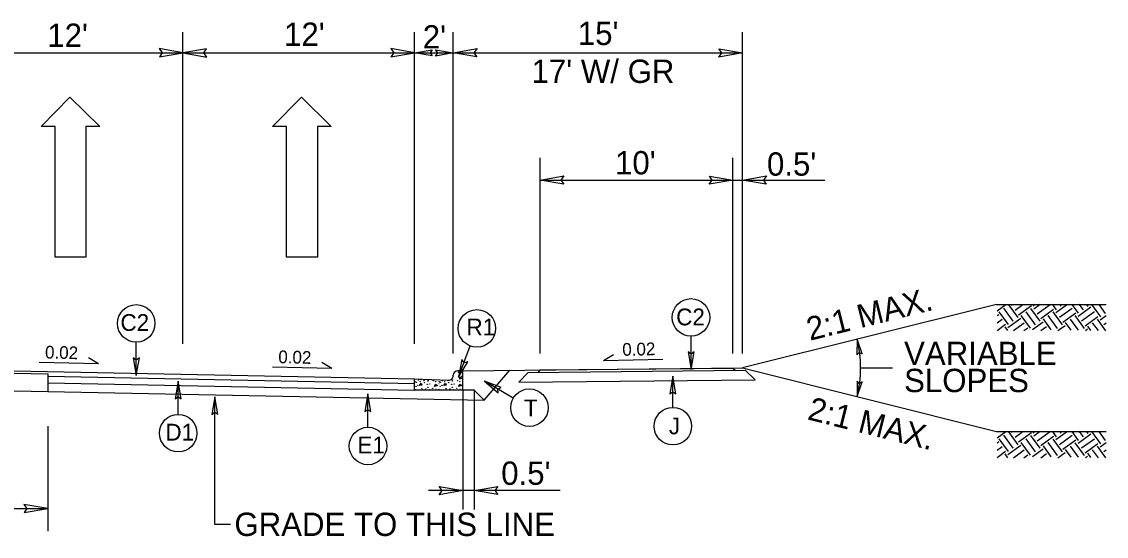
# Model space of a CAD drawing. Extents: x 3025871 to 3026431, y 707165 to 707825.
# Drawn here: x 3026374.6 to 3026430.8, y 707640.9 to 707667.6 of the extents above; entities that cross this region are included whole.
import ezdxf

# ---------------------------------------------------------------- set-up
doc = ezdxf.new("R2010")
doc.units = 0
for name, color, linetype in [('Prop Drainage Structure Junction Box with Manhole CELL', 7, 'Continuous'), ('Prop Drainage Structure Junction Box with Slab Lid TB 840 34 CELL', 7, 'Continuous'), ('Prop Drainage Structure Plot Symbol 50 Scale', 7, 'Continuous'), ('Prop Pavement Schedule Description CELL', 7, 'Continuous'), ('Sheet Data Field CELL', 7, 'Continuous'), ('Sheet Plot Border Inside CELL', 7, 'Continuous'), ('Sheet Sticker Incomplete CELL', 7, 'Continuous'), ('Sheet Typical CELL', 7, 'Continuous'), ('Typical Arrow Superelevation CELL', 7, 'Continuous'), ('Typical Grade Point Symbol CELL', 7, 'Continuous'), ('Typical Text Centerline CELL', 7, 'Continuous'), ('Typical Text Grade Point CELL', 7, 'Continuous')]:
    doc.layers.add(name, color=color, linetype=linetype)

msp = doc.modelspace()

# ---------------------------------------------------------------- linework, layer by layer
at = {"layer": 'Prop Drainage Structure Junction Box with Manhole CELL'}
msp.add_line((3026375.914, 707648.426), (3026398.523, 707647.974), dxfattribs=at)
at = {"layer": 'Prop Drainage Structure Junction Box with Slab Lid TB 840 34 CELL'}
for p, q in [((3026382.912, 707650.898), (3026382.912, 707667.04)), ((3026394.912, 707650.898), (3026394.912, 707667.04)), ((3026396.92, 707650.399), (3026396.92, 707667.04)), ((3026411.92, 707650.399), (3026411.92, 707667.04)), ((3026362.162, 707665.973), (3026394.912, 707665.973)), ((3026394.912, 707665.973), (3026411.92, 707665.973)), ((3026401.42, 707650.399), (3026401.42, 707660.529)), ((3026411.42, 707650.399), (3026411.42, 707660.529)), ((3026401.42, 707659.381), (3026416.178, 707659.381)), ((3026418.036, 707649.648), (3026419.692, 707649.648)), ((3026397.421, 707648.502), (3026397.421, 707642.305)), ((3026398.006, 707648.514), (3026398.006, 707642.305)), ((3026375.9, 707646.63), (3026375.9, 707641.192)), ((3026402.454, 707643.295), (3026395.634, 707643.294)), ((3026348.144, 707642.363), (3026375.9, 707642.363)), ((3026385.375, 707641.531), (3026384.564, 707641.531))]:
    msp.add_line(p, q, dxfattribs=at)
msp.add_arc((3026411.92, 707649.648), 6.116, 345.9638, 14.0362, dxfattribs=at)
at = {"layer": 'Prop Drainage Structure Plot Symbol 50 Scale'}
for p, q in [((3026397.421, 707649.506), (3026397.16, 707649.506)), ((3026397.421, 707648.502), (3026397.421, 707649.506)), ((3026394.912, 707648.502), (3026394.912, 707649.088)), ((3026394.912, 707649.088), (3026396.669, 707649.015)), ((3026395.174, 707648.743), (3026395.261, 707648.863)), ((3026395.295, 707648.749), (3026395.174, 707648.743)), ((3026395.261, 707648.863), (3026395.295, 707648.749)), ((3026395.942, 707648.692), (3026396.005, 707648.807)), ((3026396.108, 707648.731), (3026395.942, 707648.692)), ((3026396.005, 707648.807), (3026396.108, 707648.731)), ((3026396.428, 707648.743), (3026396.514, 707648.863)), ((3026396.548, 707648.749), (3026396.428, 707648.743)), ((3026396.514, 707648.863), (3026396.548, 707648.749)), ((3026396.919, 707649.255), (3026396.919, 707649.265)), ((3026397.195, 707648.692), (3026397.258, 707648.807)), ((3026397.362, 707648.731), (3026397.195, 707648.692)), ((3026397.23, 707649.171), (3026397.247, 707649.08)), ((3026397.385, 707649.126), (3026397.23, 707649.171)), ((3026397.247, 707649.08), (3026397.385, 707649.126)), ((3026397.258, 707648.807), (3026397.362, 707648.731)), ((3026397.421, 707648.502), (3026394.912, 707648.502))]:
    msp.add_line(p, q, dxfattribs=at)
for centre in [(3026397.19, 707649.43), (3026397.408, 707649.395), (3026394.929, 707648.841), (3026394.946, 707648.938), (3026395.002, 707648.904), (3026395.083, 707648.743), (3026395.111, 707649.029), (3026395.209, 707648.944), (3026395.255, 707649.046), (3026395.404, 707648.983), (3026395.432, 707648.881), (3026395.581, 707648.795), (3026395.61, 707648.967), (3026395.627, 707649.017), (3026395.707, 707648.823), (3026395.885, 707648.989), (3026396.005, 707648.938), (3026396.183, 707648.841), (3026396.2, 707648.938), (3026396.256, 707648.904), (3026396.336, 707648.743), (3026396.365, 707648.987), (3026396.462, 707648.944), (3026396.657, 707648.983), (3026396.686, 707648.881), (3026396.835, 707648.795), (3026396.863, 707648.967), (3026396.881, 707649.017), (3026396.961, 707648.823), (3026397.138, 707648.989), (3026397.259, 707648.938), (3026397.356, 707649.212), (3026394.923, 707648.531), (3026394.986, 707648.697), (3026395.134, 707648.508), (3026395.295, 707648.577), (3026395.501, 707648.554), (3026395.615, 707648.64), (3026395.673, 707648.526), (3026395.85, 707648.589), (3026396.022, 707648.548), (3026396.177, 707648.531), (3026396.24, 707648.697), (3026396.388, 707648.508), (3026396.548, 707648.577), (3026396.754, 707648.554), (3026396.869, 707648.64), (3026396.926, 707648.526), (3026397.104, 707648.589), (3026397.276, 707648.548)]:
    msp.add_circle(centre, 0.00805, dxfattribs=at)
for centre, start, end in [((3026397.16, 707649.265), 90, 180), ((3026396.679, 707649.255), 267.6155, 0)]:
    msp.add_arc(centre, 0.24, start, end, dxfattribs=at)
at = {"layer": 'Prop Pavement Schedule Description CELL'}
for p, q in [((3026362.16, 707649.618), (3026375.909, 707649.343)), ((3026362.162, 707649.743), (3026394.912, 707649.088)), ((3026375.909, 707649.343), (3026375.914, 707648.426)), ((3026400.804, 707649.414), (3026400.314, 707648.904)), ((3026400.804, 707649.414), (3026412.054, 707649.524)), ((3026401.42, 707649.545), (3026401.299, 707649.419)), ((3026401.42, 707649.545), (3026411.42, 707649.643)), ((3026411.42, 707649.643), (3026411.549, 707649.52)), ((3026412.049, 707649.529), (3026412.564, 707649.034)), ((3026375.91, 707649.218), (3026394.912, 707648.838)), ((3026375.912, 707648.884), (3026394.912, 707648.504)), ((3026400.319, 707648.909), (3026412.569, 707649.03)), ((3026362.143, 707648.701), (3026375.914, 707648.426))]:
    msp.add_line(p, q, dxfattribs=at)
at = {"layer": 'Sheet Data Field CELL'}
for p, q in [((3026375.555, 707662.162), (3026377.054, 707663.685)), ((3026377.054, 707663.685), (3026378.601, 707662.162)), ((3026387.555, 707662.162), (3026389.054, 707663.685)), ((3026389.054, 707663.685), (3026390.601, 707662.162)), ((3026376.28, 707662.162), (3026375.555, 707662.162)), ((3026376.28, 707655.392), (3026376.28, 707662.162)), ((3026378.601, 707662.162), (3026377.876, 707662.162)), ((3026377.876, 707662.162), (3026377.876, 707655.392)), ((3026388.28, 707662.162), (3026387.555, 707662.162)), ((3026388.28, 707655.392), (3026388.28, 707662.162)), ((3026390.601, 707662.162), (3026389.876, 707662.162)), ((3026389.876, 707662.162), (3026389.876, 707655.392)), ((3026377.876, 707655.392), (3026376.28, 707655.392)), ((3026389.876, 707655.392), (3026388.28, 707655.392))]:
    msp.add_line(p, q, dxfattribs=at)
at = {"layer": 'Sheet Plot Border Inside CELL'}
msp.add_line((3026398.006, 707648.49), (3026397.421, 707648.502), dxfattribs=at)
at = {"layer": 'Sheet Sticker Incomplete CELL'}
for p, q in [((3026378.533, 707649.853), (3026375.466, 707649.93)), ((3026378.533, 707649.853), (3026378.019, 707650.168)), ((3026390.624, 707649.612), (3026390.11, 707649.926)), ((3026404.708, 707650.04), (3026405.224, 707650.352)), ((3026404.708, 707650.04), (3026407.776, 707650.102)), ((3026390.624, 707649.612), (3026387.556, 707649.688))]:
    msp.add_line(p, q, dxfattribs=at)
at = {"layer": 'Sheet Typical CELL'}
for p, q in [((3026397.421, 707649.506), (3026411.92, 707649.648)), ((3026398.523, 707647.974), (3026399.846, 707649.53)), ((3026398.006, 707648.49), (3026398.523, 707647.974))]:
    msp.add_line(p, q, dxfattribs=at)
at = {"layer": 'Typical Grade Point Symbol CELL'}
for p, q in [((3026380.49, 707649.258), (3026380.489, 707650.982)), ((3026409.246, 707649.569), (3026409.245, 707651.294)), ((3026397.198, 707649.171), (3026397.804, 707650.785)), ((3026382.666, 707647.24), (3026382.665, 707648.965)), ((3026400.032, 707648.082), (3026398.547, 707648.958)), ((3026408.306, 707647.601), (3026408.305, 707649.216)), ((3026392.501, 707646.576), (3026392.5, 707648.301)), ((3026384.564, 707641.531), (3026384.56, 707648.158))]:
    msp.add_line(p, q, dxfattribs=at)
for centre in [(3026409.245, 707652.266), (3026380.489, 707651.954), (3026398.147, 707651.695), (3026400.869, 707647.587), (3026382.666, 707646.268), (3026408.306, 707646.629), (3026392.501, 707645.604)]:
    msp.add_circle(centre, 0.972, dxfattribs=at)
at = {"layer": 'Typical Text Centerline CELL'}
for points in [[(3026381.687, 707665.762), (3026382.912, 707665.973), (3026381.681, 707666.191), (3026381.837, 707665.973)], [(3026384.138, 707666.184), (3026382.912, 707665.973), (3026384.144, 707665.755), (3026383.988, 707665.973)], [(3026393.687, 707665.762), (3026394.912, 707665.973), (3026393.681, 707666.191), (3026393.837, 707665.973)], [(3026398.146, 707665.762), (3026396.92, 707665.973), (3026398.152, 707666.191), (3026397.996, 707665.973)], [(3026410.695, 707666.184), (3026411.92, 707665.973), (3026410.689, 707665.755), (3026410.845, 707665.973)], [(3026395.831, 707665.815), (3026394.912, 707665.973), (3026395.836, 707666.137), (3026395.719, 707665.973)], [(3026396.002, 707666.132), (3026396.921, 707665.973), (3026395.997, 707665.81), (3026396.115, 707665.973)], [(3026402.646, 707659.17), (3026401.42, 707659.381), (3026402.652, 707659.599), (3026402.496, 707659.381)], [(3026410.195, 707659.592), (3026411.42, 707659.381), (3026410.189, 707659.163), (3026410.345, 707659.381)], [(3026413.146, 707659.17), (3026411.92, 707659.381), (3026413.152, 707659.599), (3026412.996, 707659.381)], [(3026418.117, 707650.374), (3026417.853, 707651.131), (3026417.845, 707650.325), (3026417.967, 707650.447)], [(3026409.089, 707650.479), (3026409.246, 707649.569), (3026409.407, 707650.484), (3026409.245, 707650.368)], [(3026380.333, 707650.167), (3026380.49, 707649.258), (3026380.651, 707650.173), (3026380.49, 707650.056)], [(3026397.371, 707650.077), (3026397.198, 707649.171), (3026397.671, 707649.97), (3026397.479, 707649.918)], [(3026382.822, 707648.055), (3026382.665, 707648.965), (3026382.504, 707648.05), (3026382.665, 707648.166)], [(3026399.41, 707648.631), (3026398.547, 707648.958), (3026399.252, 707648.354), (3026399.234, 707648.552)], [(3026408.462, 707648.306), (3026408.305, 707649.216), (3026408.144, 707648.301), (3026408.305, 707648.417)], [(3026417.85, 707648.966), (3026417.853, 707648.165), (3026418.123, 707648.925), (3026417.968, 707648.849)], [(3026392.657, 707647.391), (3026392.5, 707648.301), (3026392.339, 707647.386), (3026392.501, 707647.502)], [(3026384.718, 707647.248), (3026384.56, 707648.158), (3026384.399, 707647.243), (3026384.561, 707647.36)], [(3026396.197, 707643.505), (3026397.422, 707643.294), (3026396.19, 707643.076), (3026396.346, 707643.294)], [(3026399.231, 707643.083), (3026398.006, 707643.294), (3026399.238, 707643.512), (3026399.081, 707643.294)], [(3026374.675, 707642.152), (3026375.9, 707642.363), (3026374.668, 707642.58), (3026374.825, 707642.363)]]:
    msp.add_lwpolyline(points, close=True, dxfattribs=at)
at = {"layer": 'Typical Text Grade Point CELL'}
for p, q in [((3026425.086, 707652.939), (3026411.92, 707649.648)), ((3026425.086, 707652.939), (3026430.77, 707652.939)), ((3026425.086, 707652.939), (3026430.77, 707652.939)), ((3026425.107, 707652.61), (3026425.567, 707652.94)), ((3026425.107, 707652.61), (3026425.567, 707652.94)), ((3026425.947, 707652.073), (3026425.467, 707652.742)), ((3026425.947, 707652.073), (3026425.467, 707652.742)), ((3026426.198, 707652.253), (3026425.717, 707652.922)), ((3026426.198, 707652.253), (3026425.717, 707652.922)), ((3026425.861, 707652.898), (3026425.921, 707652.941)), ((3026425.861, 707652.898), (3026425.921, 707652.941)), ((3026426.041, 707652.647), (3026426.452, 707652.943)), ((3026426.041, 707652.647), (3026426.452, 707652.943)), ((3026426.221, 707652.397), (3026426.889, 707652.877)), ((3026426.221, 707652.397), (3026426.889, 707652.877)), ((3026427.346, 707652.065), (3026426.866, 707652.734)), ((3026427.346, 707652.065), (3026426.866, 707652.734)), ((3026427.033, 707652.854), (3026426.968, 707652.944)), ((3026427.033, 707652.854), (3026426.968, 707652.944)), ((3026427.01, 707652.71), (3026427.337, 707652.946)), ((3026427.01, 707652.71), (3026427.337, 707652.946)), ((3026427.19, 707652.459), (3026427.858, 707652.94)), ((3026427.19, 707652.459), (3026427.858, 707652.94)), ((3026427.37, 707652.209), (3026428.038, 707652.689)), ((3026427.37, 707652.209), (3026428.038, 707652.689)), ((3026428.182, 707652.666), (3026427.979, 707652.947)), ((3026428.182, 707652.666), (3026427.979, 707652.947)), ((3026428.158, 707652.522), (3026428.753, 707652.95)), ((3026428.158, 707652.522), (3026428.753, 707652.95)), ((3026428.338, 707652.271), (3026429.007, 707652.752)), ((3026428.338, 707652.271), (3026429.007, 707652.752)), ((3026428.432, 707652.846), (3026428.359, 707652.948)), ((3026428.432, 707652.846), (3026428.359, 707652.948)), ((3026429.331, 707652.478), (3026428.999, 707652.939)), ((3026429.331, 707652.478), (3026428.999, 707652.939)), ((3026429.307, 707652.334), (3026429.975, 707652.814)), ((3026429.307, 707652.334), (3026429.975, 707652.814)), ((3026429.581, 707652.658), (3026429.37, 707652.951)), ((3026429.581, 707652.658), (3026429.37, 707652.951)), ((3026429.832, 707652.838), (3026429.759, 707652.939)), ((3026429.832, 707652.838), (3026429.759, 707652.939)), ((3026430.479, 707652.289), (3026430.012, 707652.939)), ((3026430.479, 707652.289), (3026430.012, 707652.939)), ((3026430.73, 707652.47), (3026430.392, 707652.939)), ((3026430.73, 707652.47), (3026430.392, 707652.939)), ((3026425.107, 707652.357), (3026425.192, 707652.418)), ((3026425.107, 707652.357), (3026425.192, 707652.418)), ((3026425.107, 707651.977), (3026425.373, 707652.167)), ((3026425.107, 707651.977), (3026425.373, 707652.167)), ((3026425.696, 707651.893), (3026425.216, 707652.561)), ((3026425.696, 707651.893), (3026425.216, 707652.561)), ((3026425.673, 707651.749), (3026426.341, 707652.23)), ((3026425.673, 707651.749), (3026426.341, 707652.23)), ((3026426.845, 707651.705), (3026426.365, 707652.373)), ((3026426.845, 707651.705), (3026426.365, 707652.373)), ((3026427.096, 707651.885), (3026426.615, 707652.553)), ((3026427.096, 707651.885), (3026426.615, 707652.553)), ((3026427.914, 707651.628), (3026427.513, 707652.185)), ((3026427.914, 707651.628), (3026427.513, 707652.185)), ((3026428.244, 707651.697), (3026427.764, 707652.365)), ((3026428.244, 707651.697), (3026427.764, 707652.365)), ((3026428.495, 707651.877), (3026428.015, 707652.546)), ((3026428.495, 707651.877), (3026428.015, 707652.546)), ((3026428.519, 707652.021), (3026429.187, 707652.501)), ((3026428.519, 707652.021), (3026429.187, 707652.501)), ((3026429.328, 707651.599), (3026428.913, 707652.177)), ((3026429.328, 707651.599), (3026428.913, 707652.177)), ((3026429.644, 707651.689), (3026429.163, 707652.357)), ((3026429.644, 707651.689), (3026429.163, 707652.357)), ((3026429.487, 707652.083), (3026430.156, 707652.564)), ((3026429.487, 707652.083), (3026430.156, 707652.564)), ((3026429.667, 707651.833), (3026430.336, 707652.313)), ((3026429.667, 707651.833), (3026430.336, 707652.313)), ((3026430.742, 707651.571), (3026430.312, 707652.169)), ((3026430.742, 707651.571), (3026430.312, 707652.169)), ((3026430.456, 707652.146), (3026430.77, 707652.372)), ((3026430.456, 707652.146), (3026430.77, 707652.372)), ((3026425.107, 707651.596), (3026425.553, 707651.917)), ((3026425.107, 707651.596), (3026425.553, 707651.917)), ((3026425.668, 707651.579), (3026425.529, 707651.773)), ((3026425.668, 707651.579), (3026425.529, 707651.773)), ((3026425.965, 707651.579), (3026426.521, 707651.979)), ((3026425.965, 707651.579), (3026426.521, 707651.979)), ((3026426.494, 707651.579), (3026426.701, 707651.728)), ((3026426.494, 707651.579), (3026426.701, 707651.728)), ((3026426.941, 707651.647), (3026427.49, 707652.042)), ((3026426.941, 707651.647), (3026427.49, 707652.042)), ((3026427.375, 707651.579), (3026427.67, 707651.791)), ((3026427.375, 707651.579), (3026427.67, 707651.791)), ((3026428.257, 707651.579), (3026428.639, 707651.854)), ((3026428.257, 707651.579), (3026428.639, 707651.854)), ((3026428.943, 707651.607), (3026428.662, 707651.997)), ((3026428.943, 707651.607), (3026428.662, 707651.997)), ((3026429.685, 707651.592), (3026429.787, 707651.666)), ((3026429.685, 707651.592), (3026429.787, 707651.666)), ((3026429.971, 707651.586), (3026429.811, 707651.809)), ((3026429.971, 707651.586), (3026429.811, 707651.809)), ((3026430.357, 707651.579), (3026430.061, 707651.989)), ((3026430.357, 707651.579), (3026430.061, 707651.989)), ((3026430.636, 707651.895), (3026430.77, 707651.992)), ((3026430.636, 707651.895), (3026430.77, 707651.992)), ((3026411.92, 707649.648), (3026425.086, 707646.357)), ((3026425.086, 707646.357), (3026430.77, 707646.357)), ((3026425.086, 707646.357), (3026430.77, 707646.357)), ((3026425.107, 707646.027), (3026425.567, 707646.358)), ((3026425.107, 707646.027), (3026425.567, 707646.358)), ((3026425.696, 707645.31), (3026425.216, 707645.979)), ((3026425.696, 707645.31), (3026425.216, 707645.979)), ((3026425.947, 707645.491), (3026425.467, 707646.159)), ((3026425.947, 707645.491), (3026425.467, 707646.159)), ((3026426.198, 707645.671), (3026425.717, 707646.339)), ((3026426.198, 707645.671), (3026425.717, 707646.339)), ((3026425.861, 707646.316), (3026425.921, 707646.359)), ((3026425.861, 707646.316), (3026425.921, 707646.359)), ((3026426.041, 707646.065), (3026426.452, 707646.36)), ((3026426.041, 707646.065), (3026426.452, 707646.36)), ((3026426.221, 707645.814), (3026426.889, 707646.295)), ((3026426.221, 707645.814), (3026426.889, 707646.295)), ((3026427.096, 707645.302), (3026426.615, 707645.971)), ((3026427.096, 707645.302), (3026426.615, 707645.971)), ((3026427.346, 707645.483), (3026426.866, 707646.151)), ((3026427.346, 707645.483), (3026426.866, 707646.151)), ((3026427.033, 707646.271), (3026426.968, 707646.362)), ((3026427.033, 707646.271), (3026426.968, 707646.362)), ((3026427.01, 707646.127), (3026427.337, 707646.363)), ((3026427.01, 707646.127), (3026427.337, 707646.363)), ((3026427.19, 707645.877), (3026427.858, 707646.357)), ((3026427.19, 707645.877), (3026427.858, 707646.357)), ((3026427.37, 707645.626), (3026428.038, 707646.107)), ((3026427.37, 707645.626), (3026428.038, 707646.107)), ((3026428.182, 707646.083), (3026427.979, 707646.365)), ((3026428.182, 707646.083), (3026427.979, 707646.365)), ((3026428.495, 707645.295), (3026428.015, 707645.963)), ((3026428.495, 707645.295), (3026428.015, 707645.963)), ((3026428.158, 707645.939), (3026428.753, 707646.367)), ((3026428.158, 707645.939), (3026428.753, 707646.367)), ((3026428.338, 707645.689), (3026429.007, 707646.169)), ((3026428.338, 707645.689), (3026429.007, 707646.169)), ((3026428.432, 707646.263), (3026428.359, 707646.366)), ((3026428.432, 707646.263), (3026428.359, 707646.366)), ((3026428.519, 707645.438), (3026429.187, 707645.918)), ((3026428.519, 707645.438), (3026429.187, 707645.918)), ((3026429.331, 707645.895), (3026428.999, 707646.357)), ((3026429.331, 707645.895), (3026428.999, 707646.357)), ((3026429.307, 707645.751), (3026429.975, 707646.232)), ((3026429.307, 707645.751), (3026429.975, 707646.232)), ((3026429.581, 707646.075), (3026429.37, 707646.369)), ((3026429.581, 707646.075), (3026429.37, 707646.369)), ((3026429.487, 707645.501), (3026430.156, 707645.981)), ((3026429.487, 707645.501), (3026430.156, 707645.981)), ((3026429.832, 707646.255), (3026429.759, 707646.357)), ((3026429.832, 707646.255), (3026429.759, 707646.357)), ((3026430.479, 707645.707), (3026430.012, 707646.357)), ((3026430.479, 707645.707), (3026430.012, 707646.357)), ((3026430.73, 707645.887), (3026430.392, 707646.357)), ((3026430.73, 707645.887), (3026430.392, 707646.357)), ((3026425.107, 707645.774), (3026425.192, 707645.835)), ((3026425.107, 707645.774), (3026425.192, 707645.835)), ((3026425.107, 707645.394), (3026425.373, 707645.585)), ((3026425.107, 707645.394), (3026425.373, 707645.585)), ((3026425.673, 707645.167), (3026426.341, 707645.647)), ((3026425.673, 707645.167), (3026426.341, 707645.647)), ((3026425.965, 707644.997), (3026426.521, 707645.397)), ((3026425.965, 707644.997), (3026426.521, 707645.397)), ((3026426.845, 707645.122), (3026426.365, 707645.791)), ((3026426.845, 707645.122), (3026426.365, 707645.791)), ((3026426.941, 707645.065), (3026427.49, 707645.459)), ((3026426.941, 707645.065), (3026427.49, 707645.459)), ((3026427.914, 707645.045), (3026427.513, 707645.603)), ((3026427.914, 707645.045), (3026427.513, 707645.603)), ((3026428.244, 707645.114), (3026427.764, 707645.783)), ((3026428.244, 707645.114), (3026427.764, 707645.783)), ((3026428.943, 707645.024), (3026428.662, 707645.415)), ((3026428.943, 707645.024), (3026428.662, 707645.415)), ((3026429.328, 707645.017), (3026428.913, 707645.595)), ((3026429.328, 707645.017), (3026428.913, 707645.595)), ((3026429.644, 707645.106), (3026429.163, 707645.775)), ((3026429.644, 707645.106), (3026429.163, 707645.775)), ((3026429.667, 707645.25), (3026430.336, 707645.73)), ((3026429.667, 707645.25), (3026430.336, 707645.73)), ((3026430.357, 707644.996), (3026430.061, 707645.407)), ((3026430.357, 707644.996), (3026430.061, 707645.407)), ((3026430.742, 707644.988), (3026430.312, 707645.587)), ((3026430.742, 707644.988), (3026430.312, 707645.587)), ((3026430.456, 707645.563), (3026430.77, 707645.789)), ((3026430.456, 707645.563), (3026430.77, 707645.789)), ((3026430.636, 707645.313), (3026430.77, 707645.409)), ((3026430.636, 707645.313), (3026430.77, 707645.409)), ((3026425.107, 707645.014), (3026425.553, 707645.334)), ((3026425.107, 707645.014), (3026425.553, 707645.334)), ((3026425.668, 707644.997), (3026425.529, 707645.19)), ((3026425.668, 707644.997), (3026425.529, 707645.19)), ((3026426.494, 707644.997), (3026426.701, 707645.146)), ((3026426.494, 707644.997), (3026426.701, 707645.146)), ((3026427.375, 707644.997), (3026427.67, 707645.208)), ((3026427.375, 707644.997), (3026427.67, 707645.208)), ((3026428.257, 707644.997), (3026428.639, 707645.271)), ((3026428.257, 707644.997), (3026428.639, 707645.271)), ((3026429.685, 707645.01), (3026429.787, 707645.083)), ((3026429.685, 707645.01), (3026429.787, 707645.083)), ((3026429.971, 707645.004), (3026429.811, 707645.227)), ((3026429.971, 707645.004), (3026429.811, 707645.227))]:
    msp.add_line(p, q, dxfattribs=at)

# ---------------------------------------------------------------- texts
at = {"layer": 'Prop Drainage Structure Junction Box with Slab Lid TB 840 34 CELL'}
for s, height, p in [("12'", 1.2089, (3026375.877, 707666.281)), ("12'", 1.2089, (3026388.151, 707666.335)), ("2'", 1.2089, (3026395.34, 707666.199)), ("15'", 1.2089, (3026403.378, 707666.379)), ("17' W/ GR", 1.2089, (3026400.978, 707664.414)), ("10'", 1.2089, (3026405.307, 707659.677)), ("0.5'", 1.2089, (3026413.182, 707659.61)), ("0.5'", 1.2089, (3026399.406, 707643.59)), ('GRADE TO THIS LINE', 1.20892, (3026385.577, 707640.941))]:
    msp.add_text(s, height=height, dxfattribs=at).set_placement(p)
at = {"layer": 'Sheet Sticker Incomplete CELL'}
for s, rotation, p in [('0.02 ', 1.2029, (3026405.689, 707650.276)), ('0.02', 358.5679, (3026375.755, 707650.141)), ('0.02', 358.5679, (3026387.846, 707649.899))]:
    msp.add_text(s, height=0.6583, rotation=rotation, dxfattribs=at).set_placement(p)
at = {"layer": 'Typical Arrow Superelevation CELL'}
for s, p in [('C2', (3026408.476, 707651.855)), ('C2', (3026379.672, 707651.566)), ('J', (3026408.096, 707646.209)), ('D1', (3026382.003, 707645.885)), ('E1', (3026391.956, 707645.221))]:
    msp.add_text(s, height=0.87, dxfattribs=at).set_placement(p)
for s, p in [('R1', (3026397.609, 707651.337)), ('T', (3026400.585, 707647.136))]:
    msp.add_text(s, height=0.87, rotation=360, dxfattribs=at).set_placement(p)
at = {"layer": 'Typical Text Grade Point CELL'}
for rotation, p in [(14.0362, (3026415.407, 707651.05)), (345.9638, (3026415.228, 707646.99))]:
    msp.add_text('2:1 MAX.', height=1.2089, rotation=rotation, dxfattribs=at).set_placement(p)
for s, p in [('VARIABLE', (3026420.29, 707649.796)), ('SLOPES', (3026420.29, 707648.394))]:
    msp.add_text(s, height=1.2089, dxfattribs=at).set_placement(p)

doc.saveas('drawing.dxf')
